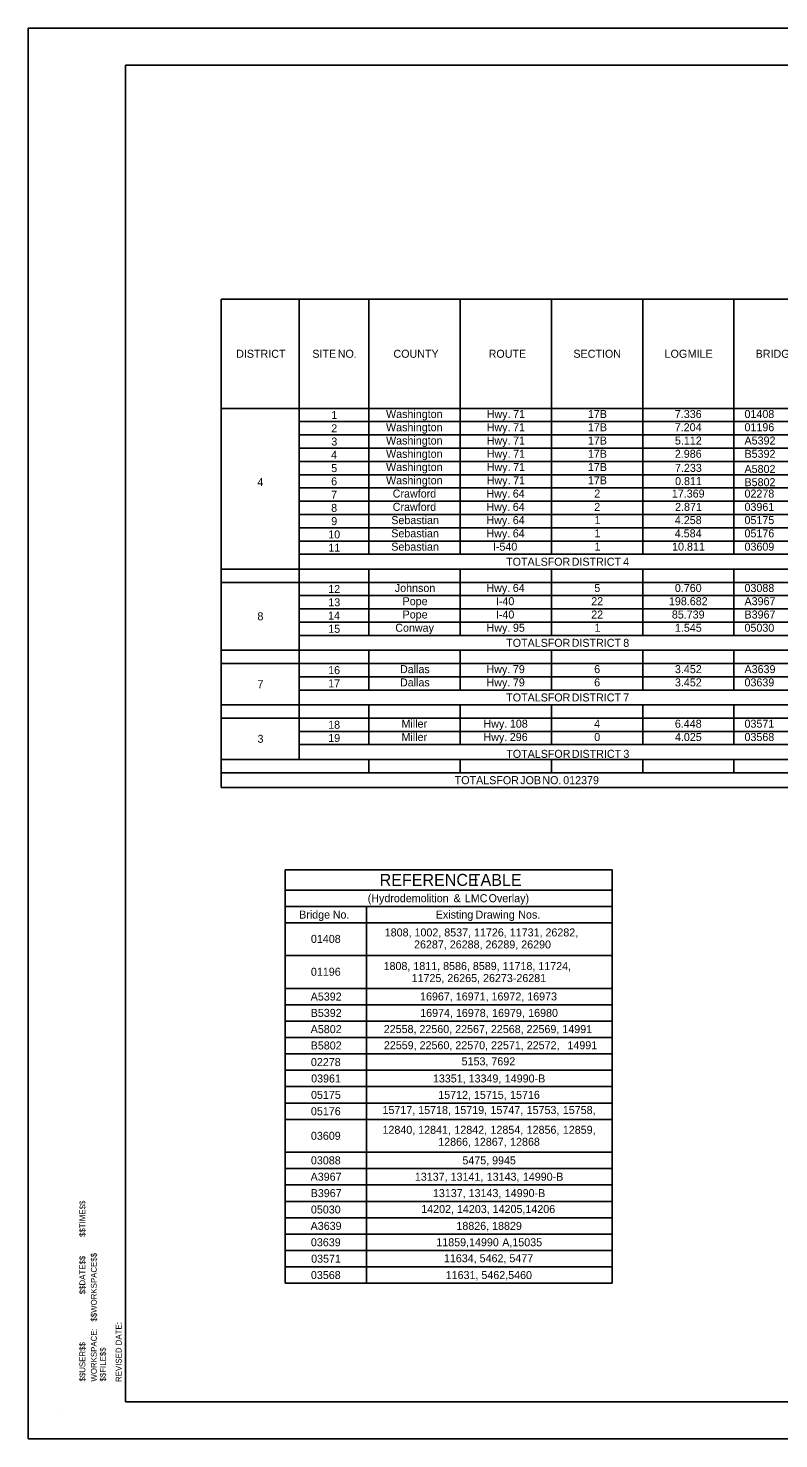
# Model space of a CAD drawing. Extents: x 16 to 1228740, y 11 to 152440.
# Drawn here: x 15.657 to 16.632, y 10.709 to 12.543 of the extents above; entities that cross this region are included whole.
import ezdxf

# ---------------------------------------------------------------- set-up
doc = ezdxf.new("R2010")
doc.units = 0
doc.layers.add('B_Text', color=7, linetype='Continuous')
doc.layers.add('R_Border', color=7, linetype='Continuous')

msp = doc.modelspace()

# ---------------------------------------------------------------- linework, layer by layer
at = {"layer": 'B_Text'}
for p, q in [((15.9076, 12.1907), (15.9076, 12.1907)), ((15.9076, 12.1907), (18.2926, 12.1907)), ((15.9076, 11.5559), (15.9076, 12.1907)), ((16.009, 11.5924), (16.009, 12.1907)), ((16.0993, 11.8591), (16.0993, 12.1907)), ((16.2179, 11.8591), (16.2179, 12.1907)), ((16.3366, 11.8591), (16.3366, 12.1907)), ((16.4552, 11.8591), (16.4552, 12.1907)), ((16.5738, 11.8591), (16.5738, 12.1907)), ((15.9076, 12.0487), (18.2926, 12.0487)), ((16.009, 12.0315), (18.2926, 12.0315)), ((16.009, 12.0142), (18.2926, 12.0142)), ((16.009, 11.997), (18.2926, 11.997)), ((16.009, 11.9797), (18.2926, 11.9797)), ((16.009, 11.9625), (18.2926, 11.9625)), ((16.009, 11.9453), (18.2926, 11.9453)), ((16.009, 11.928), (18.2926, 11.928)), ((16.009, 11.9108), (18.2926, 11.9108)), ((16.009, 11.8935), (18.2926, 11.8935)), ((16.009, 11.8763), (18.2926, 11.8763)), ((16.009, 11.8591), (18.2926, 11.8591)), ((15.9076, 11.8398), (18.2926, 11.8398)), ((16.0993, 11.7536), (16.0993, 11.8398)), ((16.2179, 11.7536), (16.2179, 11.8398)), ((16.3366, 11.7536), (16.3366, 11.8398)), ((16.4552, 11.7536), (16.4552, 11.8398)), ((16.5738, 11.7536), (16.5738, 11.8398)), ((15.9076, 11.8226), (18.2926, 11.8226)), ((16.009, 11.8053), (18.2926, 11.8053)), ((16.009, 11.7881), (18.2926, 11.7881)), ((16.009, 11.7709), (18.2926, 11.7709)), ((16.009, 11.7536), (18.2926, 11.7536)), ((15.9076, 11.7344), (18.2926, 11.7344)), ((16.0993, 11.6826), (16.0993, 11.7344)), ((16.2179, 11.6826), (16.2179, 11.7344)), ((16.3366, 11.6826), (16.3366, 11.7344)), ((16.4552, 11.6826), (16.4552, 11.7344)), ((16.5738, 11.6826), (16.5738, 11.7344)), ((15.9076, 11.7171), (18.2926, 11.7171)), ((16.009, 11.6999), (18.2926, 11.6999)), ((16.009, 11.6826), (18.2926, 11.6826)), ((15.9076, 11.6634), (18.2926, 11.6634)), ((16.0993, 11.6117), (16.0993, 11.6634)), ((16.2179, 11.6117), (16.2179, 11.6634)), ((16.3366, 11.6117), (16.3366, 11.6634)), ((16.4552, 11.6117), (16.4552, 11.6634)), ((16.5738, 11.6117), (16.5738, 11.6634)), ((15.9076, 11.6461), (18.2926, 11.6461)), ((16.009, 11.6289), (18.2926, 11.6289)), ((16.009, 11.6117), (18.2926, 11.6117)), ((15.9076, 11.5924), (18.2926, 11.5924)), ((16.0993, 11.5752), (16.0993, 11.5924)), ((16.2179, 11.5752), (16.2179, 11.5924)), ((16.3366, 11.5752), (16.3366, 11.5924)), ((16.4552, 11.5752), (16.4552, 11.5924)), ((16.5738, 11.5752), (16.5738, 11.5924)), ((15.9076, 11.5752), (18.2926, 11.5752)), ((15.9076, 11.5559), (18.2926, 11.5559)), ((15.9907, 11.4491), (15.9907, 11.4491)), ((15.9907, 11.4491), (16.4156, 11.4491)), ((15.9907, 10.9117), (15.9907, 11.4491)), ((16.4156, 10.9117), (16.4156, 11.4491)), ((15.9907, 11.4227), (16.4156, 11.4227)), ((15.9907, 11.4014), (16.4156, 11.4014)), ((16.0962, 10.9117), (16.0962, 11.4014)), ((15.9907, 11.3801), (16.4156, 11.3801)), ((15.9907, 11.3375), (16.4156, 11.3375)), ((15.9907, 11.2949), (16.4156, 11.2949)), ((15.9907, 11.2737), (16.4156, 11.2737)), ((15.9907, 11.2524), (16.4156, 11.2524)), ((15.9907, 11.2311), (16.4156, 11.2311)), ((15.9907, 11.2098), (16.4156, 11.2098)), ((15.9907, 11.1885), (16.4156, 11.1885)), ((15.9907, 11.1672), (16.4156, 11.1672)), ((15.9907, 11.1459), (16.4156, 11.1459)), ((15.9907, 11.1246), (16.4156, 11.1246)), ((15.9907, 11.082), (16.4156, 11.082)), ((15.9907, 11.0607), (16.4156, 11.0607)), ((15.9907, 11.0394), (16.4156, 11.0394)), ((15.9907, 11.0181), (16.4156, 11.0181)), ((15.9907, 10.9968), (16.4156, 10.9968)), ((15.9907, 10.9755), (16.4156, 10.9755)), ((15.9907, 10.9542), (16.4156, 10.9542)), ((15.9907, 10.933), (16.4156, 10.933)), ((15.9907, 10.9117), (16.4156, 10.9117))]:
    msp.add_line(p, q, dxfattribs=at)
at = {"layer": 'R_Border'}
for p, q in [((15.7833, 12.4948), (18.4422, 12.4948)), ((15.7833, 10.7576), (15.7833, 12.4948)), ((15.6959, 10.7451), (15.6959, 10.7451)), ((18.4422, 10.7576), (15.7833, 10.7576))]:
    msp.add_line(p, q, dxfattribs=at)
msp.add_lwpolyline([(15.6569, 12.5428), (18.4903, 12.5428), (18.4903, 10.7095), (15.6569, 10.7095)], close=True, dxfattribs=at)

# ---------------------------------------------------------------- texts
at = {"layer": 'B_Text'}
for s, height, p in [('DISTRICT', 0.0104, (15.9271, 12.1145)), ('SITE', 0.0104, (16.026, 12.1145)), (' NO.', 0.0104, (16.0552, 12.1145)), ('COUNTY', 0.0104, (16.1314, 12.1145)), ('ROUTE', 0.0104, (16.2551, 12.1145)), ('SECTION', 0.0104, (16.3652, 12.1145)), ('LOG', 0.0104, (16.4837, 12.1145)), (' MILE', 0.0104, (16.5098, 12.1145)), ('BRIDGE', 0.0104, (16.602, 12.1145)), ('1', 0.0104, (16.0508, 12.0349)), ('Washington', 0.0104, (16.1218, 12.0362)), ('Hwy.', 0.0104, (16.2526, 12.0362)), (' 71', 0.0104, (16.283, 12.0362)), ('17B', 0.0104, (16.384, 12.0362)), ('7.336', 0.0104, (16.497, 12.0362)), ('   01408', 0.0104, (16.5759, 12.0362)), ('2', 0.0104, (16.0506, 12.0176)), ('Washington', 0.0104, (16.1218, 12.019)), ('Hwy.', 0.0104, (16.2526, 12.019)), (' 71', 0.0104, (16.283, 12.019)), ('17B', 0.0104, (16.384, 12.019)), ('7.204', 0.0104, (16.4969, 12.019)), ('   01196', 0.0104, (16.5759, 12.019)), ('3', 0.0104, (16.0507, 12.0004)), ('Washington', 0.0104, (16.1218, 12.0017)), ('Hwy.', 0.0104, (16.2526, 12.0017)), (' 71', 0.0104, (16.283, 12.0017)), ('17B', 0.0104, (16.384, 12.0017)), ('5.112', 0.0104, (16.4971, 12.0017)), ('   A5392', 0.0104, (16.5759, 12.0017)), ('4', 0.0104, (16.0504, 11.9832)), ('Washington', 0.0104, (16.1218, 11.9845)), ('Hwy.', 0.0104, (16.2526, 11.9845)), (' 71', 0.0104, (16.283, 11.9845)), ('17B', 0.0104, (16.384, 11.9845)), ('2.986', 0.0104, (16.497, 11.9845)), ('   B5392', 0.0104, (16.5759, 11.9845)), ('5', 0.0104, (16.0506, 11.9659)), ('Washington', 0.0104, (16.1218, 11.9673)), ('Hwy.', 0.0104, (16.2526, 11.9673)), (' 71', 0.0104, (16.283, 11.9673)), ('17B', 0.0104, (16.384, 11.9673)), ('7.233', 0.0104, (16.4972, 11.9662)), ('   A5802', 0.0104, (16.5759, 11.9648)), ('4', 0.0104, (15.9546, 11.9477)), ('6', 0.0104, (16.0505, 11.9487)), ('Washington', 0.0104, (16.1218, 11.95)), ('Hwy.', 0.0104, (16.2526, 11.95)), (' 71', 0.0104, (16.283, 11.95)), ('17B', 0.0104, (16.384, 11.95)), ('0.811', 0.0104, (16.4973, 11.949)), ('   B5802', 0.0104, (16.5759, 11.9476)), ('7', 0.0104, (16.0505, 11.9314)), ('Crawford', 0.0104, (16.1305, 11.9328)), ('Hwy.', 0.0104, (16.2522, 11.9328)), (' 64', 0.0104, (16.2826, 11.9328)), ('2', 0.0104, (16.3923, 11.9328)), ('17.369', 0.0104, (16.4931, 11.9328)), ('   02278', 0.0104, (16.5759, 11.9328)), ('8', 0.0104, (16.0505, 11.9142)), ('Crawford', 0.0104, (16.1305, 11.9155)), ('Hwy.', 0.0104, (16.2522, 11.9155)), (' 64', 0.0104, (16.2826, 11.9155)), ('2', 0.0104, (16.3923, 11.9155)), ('2.871', 0.0104, (16.4973, 11.9155)), ('   03961', 0.0104, (16.5759, 11.9155)), ('9', 0.0104, (16.0506, 11.897)), ('Sebastian', 0.0104, (16.1286, 11.8983)), ('Hwy.', 0.0104, (16.2522, 11.8983)), (' 64', 0.0104, (16.2826, 11.8983)), ('1', 0.0104, (16.3926, 11.8983)), ('4.258', 0.0104, (16.497, 11.8983)), ('   05175', 0.0104, (16.5759, 11.8983)), ('10', 0.0104, (16.0467, 11.8797)), ('Sebastian', 0.0104, (16.1286, 11.8811)), ('Hwy.', 0.0104, (16.2522, 11.8811)), (' 64', 0.0104, (16.2826, 11.8811)), ('1', 0.0104, (16.3926, 11.8811)), ('4.584', 0.0104, (16.4969, 11.8811)), ('   05176', 0.0104, (16.5759, 11.8811)), ('11', 0.0104, (16.0469, 11.8625)), ('Sebastian', 0.0104, (16.1286, 11.8638)), ('I-540', 0.0104, (16.2606, 11.8638)), ('1', 0.0104, (16.3926, 11.8638)), ('10.811', 0.0104, (16.4934, 11.8638)), ('   03609', 0.0104, (16.5759, 11.8638)), ('TOTALS', 0.0104, (16.2778, 11.8442)), (' FOR', 0.0104, (16.3279, 11.8442)), (' DISTRICT', 0.0104, (16.3591, 11.8442)), (' 4', 0.0104, (16.426, 11.8442)), ('12', 0.0104, (16.0467, 11.8088)), ('Johnson', 0.0104, (16.1332, 11.8101)), ('Hwy.', 0.0104, (16.2522, 11.8101)), (' 64', 0.0104, (16.2826, 11.8101)), ('5', 0.0104, (16.3924, 11.8101)), ('0.760', 0.0104, (16.497, 11.8101)), ('   03088', 0.0104, (16.5759, 11.8101)), ('13', 0.0104, (16.0468, 11.7915)), ('Pope', 0.0104, (16.1433, 11.7929)), ('I-40', 0.0104, (16.2645, 11.7929)), ('22', 0.0104, (16.3884, 11.7929)), ('198.682', 0.0104, (16.4893, 11.7929)), ('   A3967', 0.0104, (16.5759, 11.7929)), ('8', 0.0104, (15.9547, 11.7733)), ('14', 0.0104, (16.0465, 11.7743)), ('Pope', 0.0104, (16.1433, 11.7756)), ('I-40', 0.0104, (16.2645, 11.7756)), ('22', 0.0104, (16.3884, 11.7756)), ('85.739', 0.0104, (16.4931, 11.7756)), ('   B3967', 0.0104, (16.5759, 11.7756)), ('15', 0.0104, (16.0467, 11.757)), ('Conway', 0.0104, (16.1338, 11.7584)), ('Hwy.', 0.0104, (16.2524, 11.7584)), (' 95', 0.0104, (16.2828, 11.7584)), ('1', 0.0104, (16.3926, 11.7584)), ('1.545', 0.0104, (16.4971, 11.7584)), ('   05030', 0.0104, (16.5759, 11.7584)), ('TOTALS', 0.0104, (16.2779, 11.7388)), (' FOR', 0.0104, (16.328, 11.7388)), (' DISTRICT', 0.0104, (16.3591, 11.7388)), (' 8', 0.0104, (16.4261, 11.7388)), ('Dallas', 0.0104, (16.1399, 11.7046)), ('Hwy.', 0.0104, (16.2523, 11.7046)), (' 79', 0.0104, (16.2827, 11.7046)), ('6', 0.0104, (16.3922, 11.7046)), ('3.452', 0.0104, (16.4971, 11.7046)), ('   A3639', 0.0104, (16.5759, 11.7046)), ('16', 0.0104, (16.0466, 11.7033)), ('Dallas', 0.0104, (16.1399, 11.6874)), ('Hwy.', 0.0104, (16.2523, 11.6874)), (' 79', 0.0104, (16.2827, 11.6874)), ('6', 0.0104, (16.3922, 11.6874)), ('3.452', 0.0104, (16.4971, 11.6874)), ('   03639', 0.0104, (16.5759, 11.6874)), ('7', 0.0104, (15.9547, 11.685)), ('17', 0.0104, (16.0466, 11.6861)), ('TOTALS', 0.0104, (16.2779, 11.6678)), (' FOR', 0.0104, (16.328, 11.6678)), (' DISTRICT', 0.0104, (16.3591, 11.6678)), (' 7', 0.0104, (16.4261, 11.6678)), ('18', 0.0104, (16.0466, 11.6323)), ('Miller', 0.0104, (16.1419, 11.6337)), ('Hwy.', 0.0104, (16.2484, 11.6337)), (' 108', 0.0104, (16.2788, 11.6337)), ('4', 0.0104, (16.3922, 11.6337)), ('6.448', 0.0104, (16.497, 11.6337)), ('   03571', 0.0104, (16.5759, 11.6337)), ('3', 0.0104, (15.9548, 11.6141)), ('19', 0.0104, (16.0467, 11.6151)), ('Miller', 0.0104, (16.1419, 11.6164)), ('Hwy.', 0.0104, (16.2484, 11.6164)), (' 296', 0.0104, (16.2787, 11.6164)), ('0', 0.0104, (16.3923, 11.6164)), ('4.025', 0.0104, (16.4971, 11.6164)), ('   03568', 0.0104, (16.5759, 11.6164)), ('TOTALS', 0.0104, (16.278, 11.5945)), (' FOR', 0.0104, (16.3281, 11.5945)), (' DISTRICT', 0.0104, (16.3593, 11.5945)), (' 3', 0.0104, (16.4263, 11.5945)), ('TOTALS', 0.0104, (16.211, 11.5603)), (' FOR', 0.0104, (16.2612, 11.5603)), (' JOB', 0.0104, (16.2923, 11.5603)), (' NO.', 0.0104, (16.321, 11.5603)), (' 012379', 0.0104, (16.3481, 11.5603)), ('REFERENCE', 0.0156, (16.1135, 11.4281)), (' TABLE', 0.0156, (16.226, 11.4281)), ('(Hydrodemolition', 0.0104, (16.098, 11.4069)), (' &', 0.0104, (16.2057, 11.4069)), (' LMC', 0.0104, (16.2203, 11.4069)), (' Overlay)', 0.0104, (16.2512, 11.4069)), ('Bridge', 0.0104, (16.0089, 11.3856)), (' No.', 0.0104, (16.0487, 11.3856)), ('Existing', 0.0104, (16.1864, 11.3856)), (' Drawing', 0.0104, (16.2341, 11.3856)), (' Nos.', 0.0104, (16.2897, 11.3856)), ('1808, 1002, 8537, 11726, 11731, 26282,', 0.0104, (16.1201, 11.3624)), ('01408', 0.0104, (16.0242, 11.354)), ('26287, 26288, 26289, 26290', 0.0104, (16.1582, 11.3468)), ('01196', 0.0104, (16.0242, 11.3113)), ('1808, 1811, 8586, 8589, 11718, 11724,', 0.0104, (16.1186, 11.3187)), ('11725, 26265, 26273-26281', 0.0104, (16.155, 11.3031)), ('A5392', 0.0104, (16.0239, 11.2791)), ('16967, 16971, 16972, 16973', 0.0104, (16.166, 11.2792)), ('B5392', 0.0104, (16.0239, 11.2578)), ('16974,', 0.0104, (16.1662, 11.2578)), (' 16978,', 0.0104, (16.2087, 11.2578)), (' 16979,', 0.0104, (16.2557, 11.2578)), (' 16980', 0.0104, (16.3026, 11.2578)), ('A5802', 0.0104, (16.0239, 11.2367)), ('22558, 22560, 22567, 22568, 22569, 14991', 0.0104, (16.1188, 11.2368)), ('B5802', 0.0104, (16.0239, 11.2155)), ('22559, 22560, 22570, 22571, 22572,', 0.0104, (16.119, 11.2158)), (' 14991', 0.0104, (16.3536, 11.2158)), ('02278', 0.0104, (16.0242, 11.1939)), ('5153, 7692', 0.0104, (16.22, 11.1949)), ('03961', 0.0104, (16.0245, 11.1726)), ('13351,', 0.0104, (16.1827, 11.1726)), (' 13349,', 0.0104, (16.2252, 11.1726)), (' 14990-B', 0.0104, (16.2722, 11.1726)), ('05175', 0.0104, (16.0243, 11.1513)), ('15712,', 0.0104, (16.1896, 11.1513)), (' 15715,', 0.0104, (16.2321, 11.1513)), (' 15716', 0.0104, (16.2791, 11.1513)), ('05176', 0.0104, (16.0242, 11.13)), ('15717,', 0.0104, (16.1172, 11.1316)), (' 15718,', 0.0104, (16.1597, 11.1316)), (' 15719,', 0.0104, (16.2067, 11.1316)), (' 15747,', 0.0104, (16.2536, 11.1316)), (' 15753,', 0.0104, (16.3006, 11.1316)), (' 15758,', 0.0104, (16.3476, 11.1316)), ('12840,', 0.0104, (16.1172, 11.1059)), (' 12841,', 0.0104, (16.1597, 11.1059)), (' 12842,', 0.0104, (16.2067, 11.1059)), (' 12854,', 0.0104, (16.2536, 11.1059)), (' 12856,', 0.0104, (16.3006, 11.1059)), (' 12859,', 0.0104, (16.3476, 11.1059)), ('03609', 0.0104, (16.0242, 11.0981)), ('12866,', 0.0104, (16.1896, 11.0903)), (' 12867,', 0.0104, (16.2321, 11.0903)), (' 12868', 0.0104, (16.2791, 11.0903)), ('03088', 0.0104, (16.0242, 11.0662)), ('5475,', 0.0104, (16.221, 11.0662)), (' 9945', 0.0104, (16.2557, 11.0662)), ('A3967', 0.0104, (16.0238, 11.0449)), ('13137,', 0.0104, (16.1592, 11.0449)), (' 13141,', 0.0104, (16.2018, 11.0449)), (' 13143,', 0.0104, (16.2487, 11.0449)), (' 14990-B', 0.0104, (16.2957, 11.0449)), ('B3967', 0.0104, (16.0239, 11.0236)), ('13137,', 0.0104, (16.1827, 11.0236)), (' 13143,', 0.0104, (16.2252, 11.0236)), (' 14990-B', 0.0104, (16.2722, 11.0236)), ('05030', 0.0104, (16.0242, 11.0023)), ('14202, 14203, 14205,14206', 0.0104, (16.1675, 11.0029)), ('A3639', 0.0104, (16.0238, 10.981)), ('18826,', 0.0104, (16.2132, 10.981)), (' 18829', 0.0104, (16.2557, 10.981)), ('03639', 0.0104, (16.0242, 10.9597)), ('11859,14990', 0.0104, (16.1871, 10.9597)), (' A,15035', 0.0104, (16.2689, 10.9597)), ('03571', 0.0104, (16.0245, 10.9384)), ('11634, 5462, 5477', 0.0104, (16.197, 10.9389)), ('03568', 0.0104, (16.0242, 10.9171)), ('11631,', 0.0104, (16.1993, 10.9171)), (' 5462,5460', 0.0104, (16.2418, 10.9171))]:
    msp.add_text(s, height=height, dxfattribs=at).set_placement(p)
at = {"layer": 'R_Border'}
for s, p in [('$$TIME$$', (15.7311, 10.9718)), ('$$DATE$$', (15.7311, 10.8973)), ('$$WORKSPACE$$', (15.746, 10.8618)), ('REVISED DATE:', (15.7782, 10.7833)), ('WORKSPACE:', (15.746, 10.7838)), ('$$USER$$', (15.7311, 10.7839)), ('$$FILE$$', (15.7578, 10.7839))]:
    msp.add_text(s, height=0.00765, rotation=90, dxfattribs=at).set_placement(p)

doc.saveas('drawing.dxf')
